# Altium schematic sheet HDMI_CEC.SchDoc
size A4; Revision: B.2
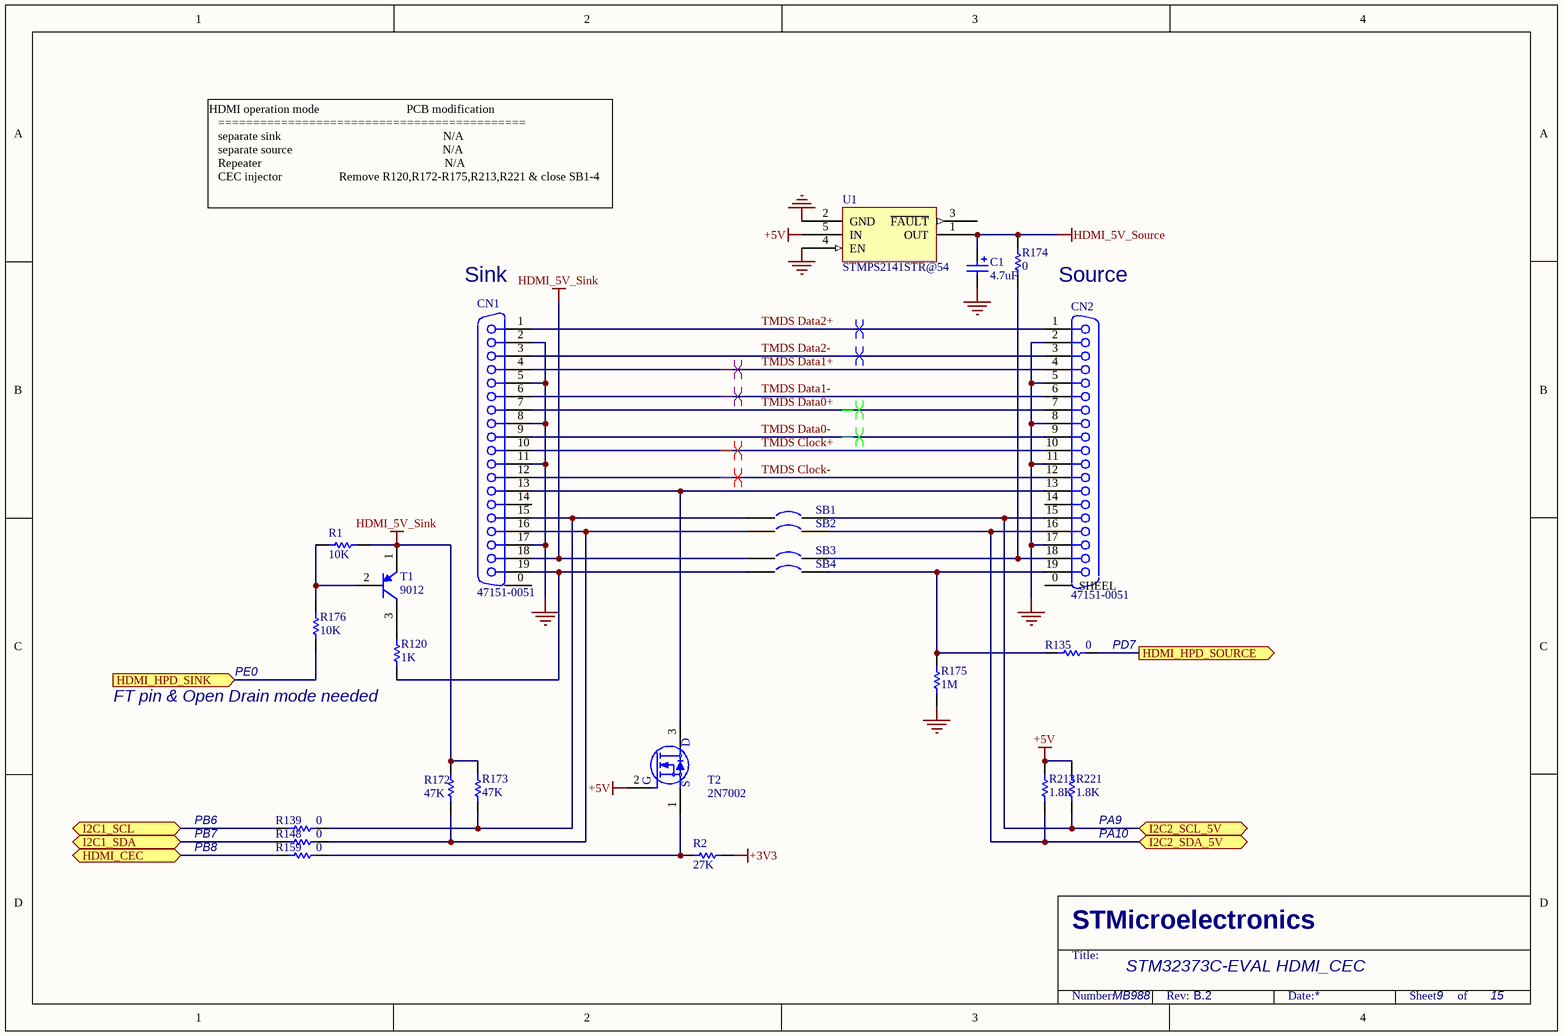
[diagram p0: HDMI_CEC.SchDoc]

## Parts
C1  4.7uF  [TAN-A]
CN1  47151-0051  [0471510051]
CN2  47151-0051  [0471510051]
R1  10K  [0603R]
R2  27K  [0603R]
R120  1K  [0603R]
R135  0  [0603R]
R139  0  [0603R]
R148  0  [0603R]
R159  0  [0603R]
R172  47K  [0603R]
R173  47K  [0603R]
R174  0  [0603R]
R175  1M  [0603R]
R176  10K  [0603R]
R213  1.8K  [0603R]
R221  1.8K  [0603R]
SB1  (no value)  [JP2_SMD]
SB2  (no value)  [JP2_SMD]
SB3  (no value)  [JP2_SMD]
SB4  (no value)  [JP2_SMD]
T1  9012  [SOT-23]
T2  2N7002  [SOT-23]
U1  STMPS2141STR@54  [SOT-23-5L]

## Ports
HDMI_CEC (bidir), HDMI_HPD_SINK (in), HDMI_HPD_SOURCE (out), I2C1_SCL (bidir), I2C1_SDA (bidir), I2C2_SCL_5V (bidir), I2C2_SDA_5V (bidir)

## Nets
+3V3: R2.2
+5V: R213.2 R221.2 T2.2(G) U1.5(IN)
GND: C1.2 CN1.2 CN1.5 CN1.8 CN1.11 CN1.17 CN2.2 CN2.5 CN2.8 CN2.11 CN2.17 R175.1 U1.2(GND) U1.4(EN)
HDMI_5V_Sink: CN1.18 R1.1 R172.2 R173.2 SB3.1 T1.1(E)
HDMI_5V_Source: C1.1 R174.1 U1.1(OUT)
HDMI_CEC: R159.2 ; port HDMI_CEC
HDMI_HPD_SINK: R176.1 ; port HDMI_HPD_SINK
HDMI_HPD_SOURCE: R135.1 ; port HDMI_HPD_SOURCE
I2C1_SCL: R139.2 ; port I2C1_SCL
I2C1_SDA: R148.2 ; port I2C1_SDA
I2C2_SCL_5V: CN2.15 R221.1 SB1.2 ; port I2C2_SCL_5V
I2C2_SDA_5V: CN2.16 R213.1 SB2.2 ; port I2C2_SDA_5V
TMDS Clock+: CN1.10 CN2.10
TMDS Clock-: CN1.12 CN2.12
TMDS Data0+: CN1.7 CN2.7
TMDS Data0-: CN1.9 CN2.9
TMDS Data1+: CN1.4 CN2.4
TMDS Data1-: CN1.6 CN2.6
TMDS Data2+: CN1.1 CN2.1
TMDS Data2-: CN1.3 CN2.3
NetCN1_13: CN1.13 CN2.13 T2.3(D)
NetCN1_15: CN1.15 R139.1 R173.1 SB1.1
NetCN1_16: CN1.16 R148.1 R172.1 SB2.1
NetCN1_19: CN1.19 R120.1 SB4.1
NetCN2_18: CN2.18 R174.2 SB3.2
NetCN2_19: CN2.19 R135.2 R175.2 SB4.2
NetR1_2: R1.2 R176.2 T1.2(B)
NetR2_1: R2.1 R159.1 T2.1(S)
NetR120_2: R120.2 T1.3(C)

Not connected (* = marked no-connect by the designer): CN1 0(SHEEL) 14; CN2 0(SHEEL) 14; U1 3(~{FAULT})

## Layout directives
differential pair: TMDS Clock+, TMDS Clock-, TMDS Data0+, TMDS Data0-, TMDS Data1+, TMDS Data1-, TMDS Data2+, TMDS Data2-

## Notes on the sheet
- HDMI operation mode                             PCB modification
  ============================================
  separate sink                                                      N/A
  separate source                                                  N/A
  Repeater                                                             N/A
  CEC injector                   Remove R120,R172-R175,R213,R221 & close SB1-4
- (near CN1) Sink
- Source
- (near R135) PD7
- (near R120) FT pin & Open Drain mode needed
- PE0
- PB8
- PB6
- PB7
- (near R221) PA9
- PA10
- STM32373C-EVAL HDMI_CEC
- MB988
- 9
- 15

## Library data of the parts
C1 = Cap Pol1: Polarized Capacitor (Radial); Value: 47uF
CN1 = 47151-0051(L)
CN2 = 47151-0051(R)
R1 R2 R135 R139 R148 R159 R172-R176 R213 R221 = Res1: Resistor; Value: 1K
R120 = Res1: Resistor
SB1-SB4 = Circuit Breaker
T1 = PNP: PNP Bipolar Transistor
U1 = STMPS2141STR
